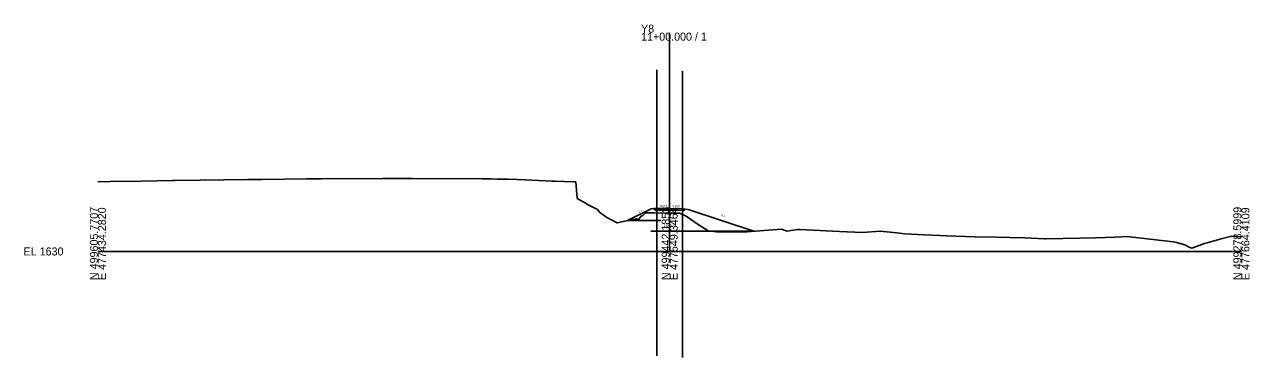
# Model space of a CAD drawing. Extents: x -26 to 403, y -10 to 2517.
# Drawn here: x -25.7 to 402.8, y 963 to 1079.3 of the extents above; entities that cross this region are included whole.
import ezdxf

# ---------------------------------------------------------------- set-up
doc = ezdxf.new("R2010")
doc.units = 0
for name, color, linetype in [('Exist Cross Section Cell', 7, 'Continuous'), ('Exist XS Center Line Elevation Label', 7, 'Continuous'), ('Exist XS Ground Line', 7, 'Continuous'), ('Prop Road Sect_ Boring - Material (Outline)', 7, 'Continuous'), ('Prop XS Dump Level', 7, 'Continuous'), ('Prop XS Earthwork Shape', 7, 'Continuous'), ('Prop XS EOT Tick Mark', 7, 'Continuous'), ('Prop XS Finish Grade', 7, 'Continuous'), ('Prop XS Finish Grade Earthwork', 7, 'Continuous'), ('Prop XS Finish Grade Pavement', 7, 'Continuous'), ('Prop XS Pvmt Edge Slope', 7, 'Continuous'), ('Prop XS SE Text', 7, 'Continuous'), ('Prop XS Side Slope Text', 7, 'Continuous'), ('Prop XS Subgrade Earthwork', 7, 'Continuous'), ('Scratch_Level_5', 7, 'Continuous')]:
    doc.layers.add(name, color=color, linetype=linetype)

msp = doc.modelspace()

# ---------------------------------------------------------------- linework, layer by layer
at = {"layer": 'Exist Cross Section Cell'}
for p, q in [((200, 1000), (200, 1076.46)), ((0, 1000), (200, 1000)), ((200, 1000), (400, 1000))]:
    msp.add_line(p, q, dxfattribs=at)
at = {"layer": 'Exist XS Ground Line'}
msp.add_lwpolyline([(0, 1024.39), (4.28, 1024.44), (15.02, 1024.6), (26.11, 1024.75), (26.82, 1024.75), (35.71, 1024.97), (52.28, 1025.11), (54, 1025.14), (57.47, 1025.16), (73, 1025.36), (78.22, 1025.39), (99.68, 1025.48), (104.3, 1025.49), (105.44, 1025.48), (109.93, 1025.49), (134.44, 1025.33), (137.27, 1025.41), (139.71, 1025.27), (140.97, 1025.3), (143.54, 1025.21), (149.53, 1024.98), (158.85, 1024.56), (159.93, 1024.54), (166.46, 1024.35), (167.13, 1024.32), (167.64, 1018.52), (170.5, 1016.91), (171.49, 1016.35), (173.1, 1015.44), (174.73, 1014.62), (175.47, 1013.77), (177.67, 1012.15), (178.44, 1011.67), (181.68, 1009.99), (183.69, 1010.52), (188.37, 1011.36), (189.15, 1011.2), (189.99, 1012.36), (190.57, 1012.55), (191.68, 1013.51), (194.46, 1013.51), (200, 1013.44), (203.41, 1013.39), (205.8, 1012.39), (209.95, 1009.48), (213.51, 1007.16), (216.35, 1006.82), (226.94, 1006.86), (239.07, 1007.82), (241.07, 1007.13), (244.68, 1007.72), (245.64, 1007.69), (247.9, 1007.59), (259.44, 1006.99), (267.41, 1006.68), (273.68, 1007.11), (279.45, 1006.51), (282.32, 1006.21), (289.13, 1005.84), (294.55, 1005.53), (296.83, 1005.51), (306.78, 1005.14), (314.22, 1004.97), (319.01, 1004.93), (324.21, 1004.76), (331.23, 1004.47), (331.6, 1004.47), (343.46, 1004.6), (348.99, 1004.72), (355.69, 1005.03), (360.1, 1005.22), (376.14, 1003.4), (377.34, 1003.18), (380.21, 1002.3), (381.78, 1001.52), (382.71, 1001.13), (386.16, 1002.42), (386.94, 1002.84), (388.07, 1003.06), (392.96, 1004.39), (396.62, 1005.3), (397.82, 1005.22), (400, 1005.11)], dxfattribs=at)
at = {"layer": 'Prop Road Sect_ Boring - Material (Outline)'}
for points in [[(195.5, 1015.02), (194.48, 1014.97), (194.96, 1014.48)], [(195.5, 1015.02), (194.48, 1014.97), (194.96, 1014.48)], [(204.5, 1014.87), (205.52, 1014.79), (205.05, 1014.32)], [(204.5, 1014.87), (205.52, 1014.79), (205.05, 1014.32)]]:
    msp.add_lwpolyline(points, close=True, dxfattribs=at)
at = {"layer": 'Prop XS Dump Level'}
for p, q in [((195.5, 1015.02), (200, 1014.96)), ((200, 1014.96), (204.5, 1014.87))]:
    msp.add_line(p, q, dxfattribs=at)
at = {"layer": 'Prop XS Earthwork Shape'}
msp.add_lwpolyline([(205.52, 1014.79), (206.5, 1014.71), (229.47, 1007.06), (226.94, 1006.86), (216.35, 1006.82), (213.51, 1007.16), (209.95, 1009.48), (205.8, 1012.39), (203.41, 1013.39), (200, 1013.44), (194.46, 1013.51), (191.68, 1013.51), (190.57, 1012.55), (189.99, 1012.36), (189.15, 1011.2), (188.37, 1011.36), (185.27, 1010.81), (193.5, 1014.92), (194.48, 1014.97), (194.96, 1014.48), (195.5, 1014.48), (200, 1014.42), (204.5, 1014.33), (205.05, 1014.32)], close=True, dxfattribs=at)
at = {"layer": 'Prop XS EOT Tick Mark'}
for p, q in [((195.5, 1015.02), (195.5, 1016.02)), ((204.5, 1014.87), (204.5, 1015.87))]:
    msp.add_line(p, q, dxfattribs=at)
at = {"layer": 'Prop XS Finish Grade'}
for p, q in [((195.5, 1015.02), (194.48, 1014.97)), ((204.5, 1014.87), (205.52, 1014.79))]:
    msp.add_line(p, q, dxfattribs=at)
at = {"layer": 'Prop XS Finish Grade Earthwork'}
for p, q in [((193.5, 1014.92), (185.27, 1010.81)), ((194.48, 1014.97), (193.5, 1014.92)), ((205.52, 1014.79), (206.5, 1014.71)), ((206.5, 1014.71), (229.47, 1007.06))]:
    msp.add_line(p, q, dxfattribs=at)
at = {"layer": 'Prop XS Finish Grade Pavement'}
for p, q in [((195.5, 1015.02), (200, 1014.96)), ((200, 1014.96), (204.5, 1014.87))]:
    msp.add_line(p, q, dxfattribs=at)
at = {"layer": 'Prop XS Pvmt Edge Slope'}
for p, q in [((195.5, 1015.02), (194.96, 1014.48)), ((204.5, 1014.87), (205.05, 1014.32))]:
    msp.add_line(p, q, dxfattribs=at)
at = {"layer": 'Prop XS Subgrade Earthwork'}
for p, q in [((194.96, 1014.48), (194.48, 1014.97)), ((195.5, 1014.48), (194.96, 1014.48)), ((200, 1014.42), (195.5, 1014.48)), ((204.5, 1014.33), (200, 1014.42)), ((204.5, 1014.33), (205.05, 1014.32)), ((205.05, 1014.32), (205.52, 1014.79))]:
    msp.add_line(p, q, dxfattribs=at)
at = {"layer": 'Scratch_Level_5'}
for p, q in [((195.5, 1063.5), (195.5, 963.5)), ((204.5, 1062.95), (204.5, 962.95)), ((185.27, 1010.81), (196.87, 1010.81)), ((229.47, 1007.06), (193.37, 1007.06))]:
    msp.add_line(p, q, dxfattribs=at)

# ---------------------------------------------------------------- texts
at = {"layer": 'Exist Cross Section Cell'}
for s, p in [('Y8', (190, 1076.46)), ('11+00.000 / 1', (190, 1073.66)), ('EL 1630', (-26, 998.6))]:
    msp.add_text(s, height=2.8, dxfattribs=at).set_placement(p)
for s, p in [('N 499605.7707', (0, 990)), ('E 477434.2820', (2.8, 990)), ('N 499442.1853', (200, 990)), ('E 477549.3464', (202.8, 990)), ('N 499278.5999', (400, 990)), ('E 477664.4109', (402.8, 990))]:
    msp.add_text(s, height=2.8, rotation=90, dxfattribs=at).set_placement(p)
at = {"layer": 'Exist XS Center Line Elevation Label'}
msp.add_text('1643.44', height=0.9, dxfattribs=at).set_placement((197.92, 1008.54))
at = {"layer": 'Prop XS Dump Level'}
for p in [(193.5, 1014.88), (206.5, 1014.67)]:
    msp.add_text('Case1', height=0.04, dxfattribs=at).set_placement(p)
at = {"layer": 'Prop XS SE Text'}
for s, rotation, p in [('0.012', 359.3316, (196.57, 1015.5)), ('0.020', 358.8542, (200.96, 1015.45))]:
    msp.add_text(s, height=0.75, rotation=rotation, dxfattribs=at).set_placement(p)
at = {"layer": 'Prop XS Side Slope Text'}
for s, rotation, p in [('2:1', 26.5651, (189.22, 1013.38)), ('3:1', 341.5651, (217.91, 1012.49))]:
    msp.add_text(s, height=0.75, rotation=rotation, dxfattribs=at).set_placement(p)

doc.saveas('drawing.dxf')
